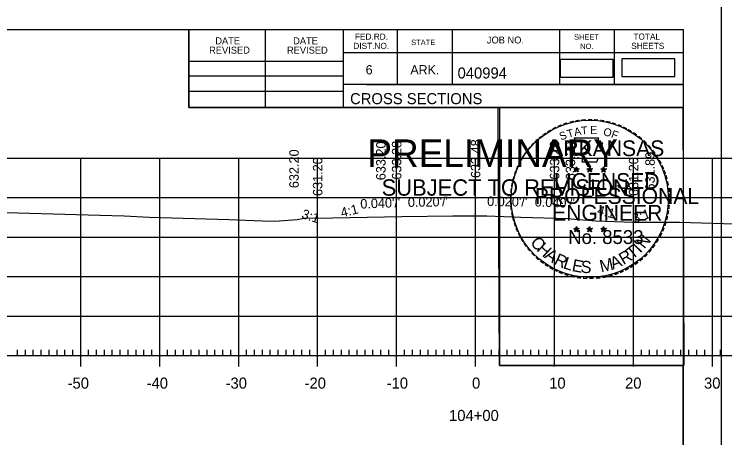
# Model space of a CAD drawing. Extents: x 1381471 to 1382703, y 370300 to 371487.
# Drawn here: x 1382078.2 to 1382168.2, y 370918.7 to 370972.4 of the extents above; entities that cross this region are included whole.
import ezdxf

# ---------------------------------------------------------------- set-up
doc = ezdxf.new("R2010")
doc.units = 0
for name, color, linetype in [('Level 26', 7, 'Continuous'), ('Level 45', 7, 'Continuous'), ('Level 6', 7, 'Continuous'), ('Level 8', 7, 'Continuous'), ('Level 9', 7, 'Continuous')]:
    doc.layers.add(name, color=color, linetype=linetype)

msp = doc.modelspace()

# ---------------------------------------------------------------- linework, layer by layer
at = {"layer": 'Level 26'}
msp.add_line((1382138.986, 370938.073), (1382138.986, 370938.073), dxfattribs=at)
for points in [[(1381834.365, 370974.304), (1382167.705, 370974.304), (1382167.705, 370760.966), (1381834.365, 370760.966)], [(1382080.692, 370970.409), (1382100.312, 370970.409), (1382100.312, 370960.529), (1382116.424, 370960.529), (1382139.624, 370960.529), (1382139.624, 370927.859), (1382162.831, 370927.859), (1382162.952, 370764.949), (1381846.772, 370764.949), (1381846.772, 370970.409)], [(1382139.484, 370960.529), (1382162.831, 370960.529), (1382162.972, 370927.859), (1382139.624, 370927.859)]]:
    msp.add_lwpolyline(points, close=True, dxfattribs=at)
msp.add_circle((1382151.064, 370948.969), 9.952, dxfattribs=at)
at = {"layer": 'Level 45'}
for p, q in [((1381996.613, 370954.122), (1382276.613, 370954.122)), ((1382086.613, 370929.122), (1382086.613, 370954.122)), ((1382096.613, 370929.122), (1382096.613, 370954.122)), ((1382106.613, 370929.122), (1382106.613, 370954.122)), ((1382116.613, 370929.122), (1382116.613, 370954.122)), ((1382126.613, 370929.122), (1382126.613, 370954.122)), ((1382136.613, 370929.122), (1382136.613, 370954.122)), ((1382146.613, 370929.122), (1382146.613, 370954.122)), ((1382156.613, 370929.122), (1382156.613, 370954.122)), ((1382166.613, 370929.122), (1382166.613, 370954.122)), ((1381996.613, 370949.122), (1382276.613, 370949.122)), ((1381996.613, 370944.122), (1382276.613, 370944.122)), ((1381996.613, 370939.122), (1382276.613, 370939.122)), ((1381996.613, 370934.122), (1382276.613, 370934.122)), ((1382086.613, 370927.722), (1382086.613, 370930.522)), ((1382096.613, 370927.722), (1382096.613, 370930.522)), ((1382106.613, 370927.722), (1382106.613, 370930.522)), ((1382116.613, 370927.722), (1382116.613, 370930.522)), ((1382126.613, 370927.722), (1382126.613, 370930.522)), ((1382136.613, 370927.722), (1382136.613, 370930.522)), ((1382146.613, 370927.722), (1382146.613, 370930.522)), ((1382156.613, 370927.722), (1382156.613, 370930.522)), ((1382166.613, 370927.722), (1382166.613, 370930.522)), ((1381996.613, 370929.122), (1382276.613, 370929.122)), ((1381996.613, 370929.122), (1382276.613, 370929.122)), ((1382078.613, 370929.122), (1382078.613, 370929.822)), ((1382079.613, 370929.122), (1382079.613, 370929.822)), ((1382080.613, 370929.122), (1382080.613, 370929.822)), ((1382081.613, 370929.122), (1382081.613, 370929.822)), ((1382082.613, 370929.122), (1382082.613, 370929.822)), ((1382083.613, 370929.122), (1382083.613, 370929.822)), ((1382084.613, 370929.122), (1382084.613, 370929.822)), ((1382085.613, 370929.122), (1382085.613, 370929.822)), ((1382087.613, 370929.122), (1382087.613, 370929.822)), ((1382088.613, 370929.122), (1382088.613, 370929.822)), ((1382089.613, 370929.122), (1382089.613, 370929.822)), ((1382090.613, 370929.122), (1382090.613, 370929.822)), ((1382091.613, 370929.122), (1382091.613, 370929.822)), ((1382092.613, 370929.122), (1382092.613, 370929.822)), ((1382093.613, 370929.122), (1382093.613, 370929.822)), ((1382094.613, 370929.122), (1382094.613, 370929.822)), ((1382095.613, 370929.122), (1382095.613, 370929.822)), ((1382097.613, 370929.122), (1382097.613, 370929.822)), ((1382098.613, 370929.122), (1382098.613, 370929.822)), ((1382099.613, 370929.122), (1382099.613, 370929.822)), ((1382100.613, 370929.122), (1382100.613, 370929.822)), ((1382101.613, 370929.122), (1382101.613, 370929.822)), ((1382102.613, 370929.122), (1382102.613, 370929.822)), ((1382103.613, 370929.122), (1382103.613, 370929.822)), ((1382104.613, 370929.122), (1382104.613, 370929.822)), ((1382105.613, 370929.122), (1382105.613, 370929.822)), ((1382107.613, 370929.122), (1382107.613, 370929.822)), ((1382108.613, 370929.122), (1382108.613, 370929.822)), ((1382109.613, 370929.122), (1382109.613, 370929.822)), ((1382110.613, 370929.122), (1382110.613, 370929.822)), ((1382111.613, 370929.122), (1382111.613, 370929.822)), ((1382112.613, 370929.122), (1382112.613, 370929.822)), ((1382113.613, 370929.122), (1382113.613, 370929.822)), ((1382114.613, 370929.122), (1382114.613, 370929.822)), ((1382115.613, 370929.122), (1382115.613, 370929.822)), ((1382117.613, 370929.122), (1382117.613, 370929.822)), ((1382118.613, 370929.122), (1382118.613, 370929.822)), ((1382119.613, 370929.122), (1382119.613, 370929.822)), ((1382120.613, 370929.122), (1382120.613, 370929.822)), ((1382121.613, 370929.122), (1382121.613, 370929.822)), ((1382122.613, 370929.122), (1382122.613, 370929.822)), ((1382123.613, 370929.122), (1382123.613, 370929.822)), ((1382124.613, 370929.122), (1382124.613, 370929.822)), ((1382125.613, 370929.122), (1382125.613, 370929.822)), ((1382127.613, 370929.122), (1382127.613, 370929.822)), ((1382128.613, 370929.122), (1382128.613, 370929.822)), ((1382129.613, 370929.122), (1382129.613, 370929.822)), ((1382130.613, 370929.122), (1382130.613, 370929.822)), ((1382131.613, 370929.122), (1382131.613, 370929.822)), ((1382132.613, 370929.122), (1382132.613, 370929.822)), ((1382133.613, 370929.122), (1382133.613, 370929.822)), ((1382134.613, 370929.122), (1382134.613, 370929.822)), ((1382135.613, 370929.122), (1382135.613, 370929.822)), ((1382137.613, 370929.122), (1382137.613, 370929.822)), ((1382138.613, 370929.122), (1382138.613, 370929.822)), ((1382139.613, 370929.122), (1382139.613, 370929.822)), ((1382140.613, 370929.122), (1382140.613, 370929.822)), ((1382141.613, 370929.122), (1382141.613, 370929.822)), ((1382142.613, 370929.122), (1382142.613, 370929.822)), ((1382143.613, 370929.122), (1382143.613, 370929.822)), ((1382144.613, 370929.122), (1382144.613, 370929.822)), ((1382145.613, 370929.122), (1382145.613, 370929.822)), ((1382147.613, 370929.122), (1382147.613, 370929.822)), ((1382148.613, 370929.122), (1382148.613, 370929.822)), ((1382149.613, 370929.122), (1382149.613, 370929.822)), ((1382150.613, 370929.122), (1382150.613, 370929.822)), ((1382151.613, 370929.122), (1382151.613, 370929.822)), ((1382152.613, 370929.122), (1382152.613, 370929.822)), ((1382153.613, 370929.122), (1382153.613, 370929.822)), ((1382154.613, 370929.122), (1382154.613, 370929.822)), ((1382155.613, 370929.122), (1382155.613, 370929.822)), ((1382157.613, 370929.122), (1382157.613, 370929.822)), ((1382158.613, 370929.122), (1382158.613, 370929.822)), ((1382159.613, 370929.122), (1382159.613, 370929.822)), ((1382160.613, 370929.122), (1382160.613, 370929.822)), ((1382161.613, 370929.122), (1382161.613, 370929.822)), ((1382162.613, 370929.122), (1382162.613, 370929.822)), ((1382163.613, 370929.122), (1382163.613, 370929.822)), ((1382164.613, 370929.122), (1382164.613, 370929.822)), ((1382165.613, 370929.122), (1382165.613, 370929.822)), ((1382167.613, 370929.122), (1382167.613, 370929.822))]:
    msp.add_line(p, q, dxfattribs=at)
msp.add_lwpolyline([(1382074.182, 370947.329), (1382089.015, 370946.892), (1382092.127, 370946.803), (1382095.267, 370946.66), (1382105.36, 370946.356), (1382109.631, 370946.199), (1382111.173, 370946.149), (1382114.008, 370946.349), (1382114.907, 370946.528), (1382118.481, 370946.563), (1382127.282, 370946.748), (1382133.744, 370946.801), (1382138.018, 370946.81), (1382142.349, 370946.664), (1382148.295, 370946.474), (1382149.579, 370946.364), (1382150.902, 370946.28), (1382151.845, 370946.187), (1382156.58, 370946.031), (1382162.425, 370945.992), (1382172.183, 370945.724)], dxfattribs=at)
at = {"layer": 'Level 6'}
for p, q in [((1381846.772, 370970.409), (1382162.952, 370970.409)), ((1382100.312, 370960.529), (1382100.312, 370970.409)), ((1382109.992, 370960.529), (1382109.992, 370970.409)), ((1382119.852, 370970.409), (1382119.852, 370960.529)), ((1382126.692, 370970.409), (1382126.692, 370963.469)), ((1382133.632, 370970.409), (1382133.632, 370963.469)), ((1382147.212, 370970.409), (1382147.212, 370963.469)), ((1382154.152, 370970.409), (1382154.152, 370963.469)), ((1382162.952, 370764.949), (1382162.952, 370970.409)), ((1382162.952, 370967.469), (1382119.852, 370967.469)), ((1382162.952, 370967.489), (1382162.952, 370967.489)), ((1382100.312, 370966.389), (1382119.852, 370966.389)), ((1382100.312, 370964.529), (1382119.852, 370964.529)), ((1382162.952, 370963.469), (1382119.852, 370963.469)), ((1382122.812, 370963.469), (1382162.952, 370963.469)), ((1382100.312, 370962.589), (1382119.852, 370962.589)), ((1382162.952, 370960.529), (1382100.312, 370960.529))]:
    msp.add_line(p, q, dxfattribs=at)
for points in [[(1382147.299, 370964.4), (1382154.01, 370964.4), (1382154.01, 370966.637), (1382147.299, 370966.637)], [(1382155.106, 370964.474), (1382161.817, 370964.474), (1382161.817, 370966.711), (1382155.106, 370966.711)]]:
    msp.add_lwpolyline(points, close=True, dxfattribs=at)
at = {"layer": 'Level 8'}
for p, q in [((1382149.037, 370952.784), (1382149.386, 370952.673)), ((1382149.037, 370952.784), (1382149.29, 370952.739)), ((1382149.037, 370952.784), (1382149.274, 370952.662)), ((1382149.17, 370952.376), (1382149.386, 370952.673)), ((1382149.17, 370952.376), (1382149.296, 370952.62)), ((1382149.17, 370952.376), (1382149.384, 370952.593)), ((1382149.386, 370953.038), (1382149.345, 370952.786)), ((1382149.599, 370952.376), (1382149.384, 370952.59)), ((1382149.386, 370952.673), (1382149.386, 370953.038)), ((1382149.386, 370953.038), (1382149.435, 370952.788)), ((1382149.733, 370952.784), (1382149.386, 370952.673)), ((1382149.599, 370952.376), (1382149.386, 370952.673)), ((1382149.733, 370952.784), (1382149.447, 370952.735)), ((1382149.599, 370952.376), (1382149.462, 370952.667)), ((1382149.733, 370952.784), (1382149.529, 370952.682)), ((1382150.707, 370952.784), (1382151.056, 370952.673)), ((1382150.707, 370952.784), (1382150.96, 370952.739)), ((1382150.707, 370952.784), (1382150.944, 370952.662)), ((1382150.84, 370952.376), (1382151.056, 370952.673)), ((1382150.84, 370952.376), (1382150.966, 370952.62)), ((1382150.84, 370952.376), (1382151.054, 370952.593)), ((1382151.056, 370953.038), (1382151.015, 370952.786)), ((1382151.269, 370952.376), (1382151.054, 370952.59)), ((1382151.056, 370952.673), (1382151.056, 370953.038)), ((1382151.056, 370953.038), (1382151.105, 370952.788)), ((1382151.403, 370952.784), (1382151.056, 370952.673)), ((1382151.269, 370952.376), (1382151.056, 370952.673)), ((1382151.403, 370952.784), (1382151.117, 370952.735)), ((1382151.269, 370952.376), (1382151.132, 370952.667)), ((1382151.403, 370952.784), (1382151.199, 370952.682)), ((1382152.471, 370952.772), (1382152.82, 370952.661)), ((1382152.471, 370952.772), (1382152.724, 370952.727)), ((1382152.471, 370952.772), (1382152.708, 370952.65)), ((1382152.604, 370952.364), (1382152.82, 370952.661)), ((1382152.604, 370952.364), (1382152.73, 370952.608)), ((1382152.604, 370952.364), (1382152.818, 370952.581)), ((1382152.82, 370953.026), (1382152.779, 370952.774)), ((1382153.033, 370952.364), (1382152.818, 370952.578)), ((1382152.82, 370952.661), (1382152.82, 370953.026)), ((1382152.82, 370953.026), (1382152.869, 370952.776)), ((1382153.167, 370952.772), (1382152.82, 370952.661)), ((1382153.033, 370952.364), (1382152.82, 370952.661)), ((1382153.167, 370952.772), (1382152.881, 370952.723)), ((1382153.033, 370952.364), (1382152.896, 370952.655)), ((1382153.167, 370952.772), (1382152.963, 370952.67)), ((1382149.382, 370945.465), (1382149.341, 370945.213)), ((1382149.382, 370945.1), (1382149.382, 370945.465)), ((1382149.382, 370945.465), (1382149.431, 370945.215)), ((1382151.051, 370945.465), (1382151.01, 370945.213)), ((1382151.051, 370945.1), (1382151.051, 370945.465)), ((1382151.051, 370945.465), (1382151.1, 370945.215)), ((1382152.818, 370945.455), (1382152.777, 370945.203)), ((1382152.818, 370945.09), (1382152.818, 370945.455)), ((1382152.818, 370945.455), (1382152.867, 370945.205)), ((1382149.033, 370945.211), (1382149.382, 370945.1)), ((1382149.033, 370945.211), (1382149.286, 370945.166)), ((1382149.033, 370945.211), (1382149.27, 370945.089)), ((1382149.166, 370944.803), (1382149.382, 370945.1)), ((1382149.166, 370944.803), (1382149.292, 370945.047)), ((1382149.166, 370944.803), (1382149.38, 370945.02)), ((1382149.595, 370944.803), (1382149.38, 370945.017)), ((1382149.729, 370945.211), (1382149.382, 370945.1)), ((1382149.595, 370944.803), (1382149.382, 370945.1)), ((1382149.729, 370945.211), (1382149.443, 370945.162)), ((1382149.595, 370944.803), (1382149.458, 370945.094)), ((1382149.729, 370945.211), (1382149.525, 370945.109)), ((1382150.702, 370945.211), (1382151.051, 370945.1)), ((1382150.702, 370945.211), (1382150.955, 370945.166)), ((1382150.702, 370945.211), (1382150.939, 370945.089)), ((1382150.835, 370944.803), (1382151.051, 370945.1)), ((1382150.835, 370944.803), (1382150.961, 370945.047)), ((1382150.835, 370944.803), (1382151.049, 370945.02)), ((1382151.264, 370944.803), (1382151.049, 370945.017)), ((1382151.398, 370945.211), (1382151.051, 370945.1)), ((1382151.264, 370944.803), (1382151.051, 370945.1)), ((1382151.398, 370945.211), (1382151.112, 370945.162)), ((1382151.264, 370944.803), (1382151.127, 370945.094)), ((1382151.398, 370945.211), (1382151.194, 370945.109)), ((1382152.469, 370945.201), (1382152.818, 370945.09)), ((1382152.469, 370945.201), (1382152.722, 370945.156)), ((1382152.469, 370945.201), (1382152.706, 370945.079)), ((1382152.602, 370944.793), (1382152.818, 370945.09)), ((1382152.602, 370944.793), (1382152.728, 370945.037)), ((1382152.602, 370944.793), (1382152.816, 370945.01)), ((1382153.031, 370944.793), (1382152.816, 370945.007)), ((1382153.165, 370945.201), (1382152.818, 370945.09)), ((1382153.031, 370944.793), (1382152.818, 370945.09)), ((1382153.165, 370945.201), (1382152.879, 370945.152)), ((1382153.031, 370944.793), (1382152.894, 370945.084)), ((1382153.165, 370945.201), (1382152.961, 370945.099))]:
    msp.add_line(p, q, dxfattribs=at)
for points in [[(1382149.078, 370956.662), (1382149.347, 370955.835)], [(1382152.589, 370955.74), (1382152.731, 370956.024), (1382152.046, 370956), (1382152.194, 370956.662), (1382149.078, 370956.662)], [(1382149.57, 370954.239), (1382149.57, 370954.152), (1382150.133, 370954.133), (1382150.079, 370953.66), (1382151.949, 370953.66), (1382152.15, 370954.196)], [(1382149.386, 370953.038), (1382149.599, 370952.376), (1382149.037, 370952.784), (1382149.733, 370952.784), (1382149.17, 370952.376), (1382149.386, 370953.038)], [(1382151.056, 370953.038), (1382151.269, 370952.376), (1382150.707, 370952.784), (1382151.403, 370952.784), (1382150.84, 370952.376), (1382151.056, 370953.038)], [(1382152.82, 370953.026), (1382153.033, 370952.364), (1382152.471, 370952.772), (1382153.167, 370952.772), (1382152.604, 370952.364), (1382152.82, 370953.026)], [(1382149.382, 370945.465), (1382149.595, 370944.803), (1382149.033, 370945.211), (1382149.729, 370945.211), (1382149.166, 370944.803), (1382149.382, 370945.465)], [(1382151.051, 370945.465), (1382151.264, 370944.803), (1382150.702, 370945.211), (1382151.398, 370945.211), (1382150.835, 370944.803), (1382151.051, 370945.465)], [(1382152.818, 370945.455), (1382153.031, 370944.793), (1382152.469, 370945.201), (1382153.165, 370945.201), (1382152.602, 370944.793), (1382152.818, 370945.455)]]:
    msp.add_lwpolyline(points, dxfattribs=at)
for centre, radius in [((1382149.385, 370952.672), 0.172), ((1382149.385, 370952.672), 0.145), ((1382149.385, 370952.672), 0.116), ((1382149.385, 370952.672), 0.0991), ((1382149.385, 370952.672), 0.0747), ((1382149.385, 370952.672), 0.0495), ((1382149.385, 370952.672), 0.0296), ((1382151.055, 370952.672), 0.172), ((1382151.055, 370952.672), 0.145), ((1382151.055, 370952.672), 0.116), ((1382151.055, 370952.672), 0.0991), ((1382151.055, 370952.672), 0.0747), ((1382151.055, 370952.672), 0.0495), ((1382151.055, 370952.672), 0.0296), ((1382152.819, 370952.66), 0.172), ((1382152.819, 370952.66), 0.145), ((1382152.819, 370952.66), 0.116), ((1382152.819, 370952.66), 0.0991), ((1382152.819, 370952.66), 0.0747), ((1382152.819, 370952.66), 0.0495), ((1382152.819, 370952.66), 0.0296), ((1382149.381, 370945.099), 0.172), ((1382151.05, 370945.099), 0.172), ((1382149.381, 370945.099), 0.145), ((1382149.381, 370945.099), 0.116), ((1382149.381, 370945.099), 0.0991), ((1382149.381, 370945.099), 0.0747), ((1382149.381, 370945.099), 0.0495), ((1382149.381, 370945.099), 0.0296), ((1382151.05, 370945.099), 0.145), ((1382151.05, 370945.099), 0.116), ((1382151.05, 370945.099), 0.0991), ((1382151.05, 370945.099), 0.0747), ((1382151.05, 370945.099), 0.0495), ((1382151.05, 370945.099), 0.0296), ((1382152.817, 370945.089), 0.172), ((1382152.817, 370945.089), 0.145), ((1382152.817, 370945.089), 0.116), ((1382152.817, 370945.089), 0.0991), ((1382152.817, 370945.089), 0.0747), ((1382152.817, 370945.089), 0.0495), ((1382152.817, 370945.089), 0.0296)]:
    msp.add_circle(centre, radius, dxfattribs=at)

# ---------------------------------------------------------------- texts
at = {"layer": 'Level 45'}
for s, rotation, p in [('633.20', 90, (1382125.213, 370951.324)), ('633.28', 90, (1382127.213, 370951.404)), ('633.48', 90, (1382137.213, 370951.604)), ('633.28', 90, (1382147.213, 370951.404)), ('633.20', 90, (1382149.213, 370951.324)), ('632.20', 90, (1382114.218, 370950.322)), ('631.89', 90, (1382159.292, 370950.017)), ('631.20', 90, (1382117.213, 370949.324)), ('631.20', 90, (1382157.213, 370949.324)), ("0.040'/'", 2.29061, (1382122.034, 370947.721)), ("0.020'/'", 1.14576, (1382128.042, 370947.932)), ("0.020'/'", 358.85424, (1382138.062, 370948.075)), ("0.040'/'", 357.70939, (1382144.074, 370948.006)), ('4:1', 14.03624, (1382119.685, 370946.607)), ('4:1', 345.96376, (1382151.928, 370947.01)), ('3:1', 341.56522, (1382114.485, 370946.56)), ('3:1', 18.43493, (1382156.706, 370945.882))]:
    msp.add_text(s, height=1.2, rotation=rotation, dxfattribs=at).set_placement(p)
for s, p in [('-50', (1382084.954, 370924.922)), ('-40', (1382094.954, 370924.922)), ('-30', (1382104.954, 370924.922)), ('-20', (1382114.954, 370924.922)), ('-10', (1382125.351, 370924.922)), ('0', (1382136.156, 370924.922)), ('10', (1382145.924, 370924.922)), ('20', (1382155.528, 370924.922)), ('30', (1382165.528, 370924.922)), ('104+00', (1382133.246, 370920.822))]:
    msp.add_text(s, height=1.4, dxfattribs=at).set_placement(p)
at = {"layer": 'Level 6'}
for s, height, p in [('FED.RD.', 0.7819, (1382121.332, 370969.129)), ('SHEET', 0.684, (1382149.072, 370969.129)), ('TOTAL', 0.7819, (1382156.592, 370969.129)), ('DATE', 0.8792, (1382103.65, 370968.545)), ('DATE', 0.8792, (1382113.51, 370968.545)), ('DIST.NO.', 0.7819, (1382121.132, 370967.949)), ('STATE', 0.684, (1382128.452, 370968.449)), ('JOB NO.', 0.8792, (1382138.032, 370968.649)), ('SHEETS', 0.7819, (1382156.312, 370967.949)), ('REVISED', 0.8792, (1382102.87, 370967.365)), ('REVISED', 0.8792, (1382112.73, 370967.365)), ('NO.', 0.684, (1382149.852, 370967.949)), ('6', 1.172, (1382122.692, 370964.729)), ('ARK.', 1.1723, (1382128.352, 370964.729)), ('040994', 1.4, (1382134.328, 370964.208)), ('CROSS SECTIONS', 1.4, (1382120.716, 370960.959))]:
    msp.add_text(s, height=height, rotation=360, dxfattribs=at).set_placement(p)
at = {"layer": 'Level 8'}
for s, height, rotation, p in [('-', 1.6, 13.63015, (1382148.576, 370958.03)), ('-', 1.6, 10.21935, (1382149.254, 370958.192)), ('-', 1.6, 5.89682, (1382149.983, 370958.302)), ('-', 1.6, 0.18623, (1382150.755, 370958.374)), ('-', 1.6, 357.74304, (1382151.478, 370958.361)), ('-', 1.6, 352.16172, (1382152.222, 370958.305)), ('-', 1.6, 347.20489, (1382152.941, 370958.191)), ('-', 1.6, 28.79182, (1382146.559, 370957.203)), ('-', 1.6, 24.30721, (1382147.192, 370957.52)), ('-', 1.6, 19.17608, (1382147.826, 370957.789)), ('A', 1, 11.21318, (1382149.173, 370956.922)), ('T', 1, 6.02276, (1382150.022, 370957.088)), ('E', 1, 0.83234, (1382151.127, 370957.198)), ('O', 1, 350.4515, (1382152.731, 370956.988)), ('-', 1.6, 342.3362, (1382153.576, 370958.036)), ('-', 1.6, 337.85509, (1382154.311, 370957.813)), ('-', 1.6, 334.12109, (1382154.942, 370957.542)), ('-', 1.6, 38.95066, (1382144.908, 370956.06)), ('-', 1.6, 36.23174, (1382145.384, 370956.438)), ('-', 1.6, 34.06357, (1382145.962, 370956.833)), ('S', 1, 21.59401, (1382147.433, 370956.34)), ('T', 1, 16.4036, (1382148.347, 370956.671)), ('F', 1, 340.07066, (1382153.685, 370956.76)), ('-', 1.6, 329.64089, (1382155.521, 370957.259)), ('-', 1.6, 325.86266, (1382156.164, 370956.898)), ('-', 1.6, 48.42305, (1382144.027, 370955.165)), ('-', 1.6, 42.96224, (1382144.475, 370955.643)), ('ARKANSAS', 2, 360, (1382145.931, 370954.374)), ('-', 1.6, 320.52971, (1382156.774, 370956.472)), ('-', 1.6, 315.57859, (1382157.373, 370955.984)), ('-', 1.6, 50.61417, (1382143.624, 370954.679)), ('-', 1.6, 309.87973, (1382157.942, 370955.434)), ('-', 1.6, 306.65218, (1382158.467, 370954.832)), ('-', 1.6, 58.07063, (1382142.886, 370953.585)), ('-', 1.6, 54.23247, (1382143.211, 370954.112)), ('-', 1.4, 303.67529, (1382158.953, 370954.264)), ('-', 1.6, 62.87135, (1382142.573, 370952.971)), ('-', 1.6, 299.66835, (1382159.272, 370953.657)), ('-', 1.6, 72.39447, (1382142.095, 370951.73)), ('-', 1.6, 67.77427, (1382142.314, 370952.36)), ('DWB', 0.01, 360, (1382149.373, 370952.668)), ('DWB', 0.01, 360, (1382151.043, 370952.668)), ('DWB', 0.01, 360, (1382152.807, 370952.657)), ('-', 1.6, 294.66279, (1382159.596, 370953.045)), ('-', 1.6, 290.57283, (1382159.853, 370952.468)), ('-', 1.6, 75.46096, (1382141.898, 370951.016)), ('LICENSED', 2, 360, (1382146.528, 370950.225)), ('-', 1.6, 285.12326, (1382160.087, 370951.888)), ('-', 1.6, 81.20126, (1382141.766, 370950.303)), ('-', 1.6, 280.54934, (1382160.287, 370951.146)), ('-', 1.6, 85.18634, (1382141.69, 370949.612)), ('PROFESSIONAL', 2, 360, (1382144.105, 370948.321)), ('-', 1.6, 276.59616, (1382160.449, 370950.378)), ('-', 1.6, 89.06224, (1382141.665, 370948.911)), ('-', 1.6, 274.33011, (1382160.509, 370949.656)), ('-', 1.6, 269.94067, (1382160.543, 370949.024)), ('-', 1.6, 94.19588, (1382141.7, 370948.186)), ('-', 1.6, 98.94793, (1382141.772, 370947.519)), ('ENGINEER', 2, 360, (1382146.292, 370946.196)), ('-', 1.6, 263.5172, (1382160.524, 370948.358)), ('-', 1.6, 101.71495, (1382141.907, 370946.786)), ('-', 1.6, 260.99529, (1382160.453, 370947.704)), ('-', 1.6, 105.45785, (1382142.069, 370946.191)), ('-', 1.6, 255.7626, (1382160.343, 370947.026)), ('-', 1.6, 109.08742, (1382142.284, 370945.56)), ('-', 1.6, 114.06432, (1382142.538, 370944.964)), ('-', 1.6, 247.88866, (1382159.939, 370945.633)), ('-', 1.6, 252.86809, (1382160.162, 370946.306)), ('-', 1.6, 115.72885, (1382142.843, 370944.346)), ('No. 8533', 1.757, 360, (1382148.334, 370943.245)), ('DWB', 0.01, 360, (1382149.369, 370945.095)), ('DWB', 0.01, 360, (1382151.038, 370945.095)), ('DWB', 0.01, 360, (1382152.805, 370945.085)), ('N', 1.54, 50.78344, (1382157.971, 370942.544)), ('-', 1.6, 244.61971, (1382159.677, 370945.004)), ('-', 1.6, 120.44712, (1382143.2, 370943.76)), ('C', 1.54, 309.95483, (1382143.456, 370943.392)), ('H', 1.54, 317.38726, (1382144.242, 370942.454)), ('-', 1.6, 239.07125, (1382159.283, 370944.252)), ('-', 1.6, 125.89344, (1382143.603, 370943.199)), ('-', 1.6, 130.71812, (1382144.065, 370942.647)), ('T', 1.54, 38.42805, (1382156.437, 370941.215)), ('I', 1.54, 46.30332, (1382157.448, 370942.024)), ('-', 1.6, 231.25377, (1382158.451, 370943.033)), ('-', 1.6, 233.84524, (1382158.881, 370943.599)), ('-', 1.6, 134.22381, (1382144.582, 370942.102)), ('A', 1.54, 325.55777, (1382145.237, 370941.551)), ('R', 1.54, 334.31873, (1382146.435, 370940.75)), ('A', 1.54, 21.7918, (1382153.992, 370940.001)), ('R', 1.54, 30.55277, (1382155.324, 370940.552)), ('-', 1.6, 225.76533, (1382157.972, 370942.469)), ('-', 1.6, 138.93382, (1382145.107, 370941.638)), ('-', 1.6, 144.64634, (1382145.663, 370941.232)), ('L', 1.54, 342.19401, (1382147.604, 370940.193)), ('E', 1.54, 349.33121, (1382148.722, 370939.831)), ('S', 1.54, 356.46841, (1382149.875, 370939.611)), ('M', 1.54, 12.44038, (1382152.496, 370939.645)), ('-', 1.6, 215.73633, (1382156.901, 370941.488)), ('-', 1.6, 221.08509, (1382157.45, 370941.96)), ('-', 1.6, 148.08978, (1382146.224, 370940.861)), ('-', 1.6, 151.57039, (1382146.803, 370940.536)), ('-', 1.6, 154.60019, (1382147.325, 370940.289)), ('-', 1.6, 204.25161, (1382155.185, 370940.436)), ('-', 1.6, 207.35684, (1382155.809, 370940.755)), ('-', 1.6, 212.24909, (1382156.367, 370941.101)), ('-', 1.6, 158.56121, (1382147.949, 370940.035)), ('-', 1.6, 162.79826, (1382148.636, 370939.822)), ('-', 1.6, 167.55551, (1382149.351, 370939.658)), ('-', 1.6, 173.11546, (1382150.123, 370939.548)), ('-', 1.6, 176.51827, (1382150.871, 370939.495)), ('-', 1.6, 181.59176, (1382151.615, 370939.514)), ('-', 1.6, 185.81666, (1382152.424, 370939.59)), ('-', 1.6, 191.28576, (1382153.16, 370939.722)), ('-', 1.6, 195.47429, (1382153.889, 370939.921)), ('-', 1.6, 200.71842, (1382154.566, 370940.163))]:
    msp.add_text(s, height=height, rotation=rotation, dxfattribs=at).set_placement(p)
at = {"layer": 'Level 9'}
for s, height, p in [('PRELIMINARY', 3.5, (1382122.903, 370952.992)), ('DWB', 0.01, (1382123.65, 370954.841)), ('SUBJECT TO REVISION', 2.07511, (1382124.712, 370949.363))]:
    msp.add_text(s, height=height, rotation=360, dxfattribs=at).set_placement(p)

doc.saveas('drawing.dxf')
